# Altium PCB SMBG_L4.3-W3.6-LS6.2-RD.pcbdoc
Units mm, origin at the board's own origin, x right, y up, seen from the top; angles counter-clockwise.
Board outline 20.26 x 16.58 mm, 2 copper layers (Top Layer, Bottom Layer), stack 0 mm thick; 1 components, 0 nets, 2 pads, 0 vias.
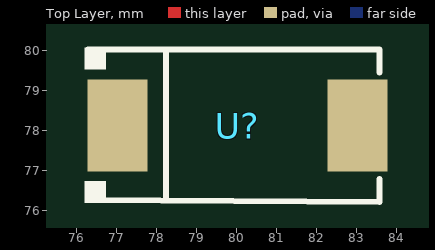
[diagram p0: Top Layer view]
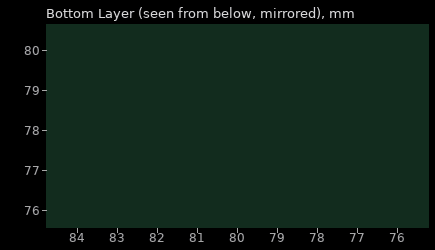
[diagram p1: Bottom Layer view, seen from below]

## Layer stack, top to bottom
Top Layer: signal copper (thickness not stored)
Bottom Layer: signal copper (thickness not stored)

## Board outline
90.112,69.85 69.85,69.85 69.85,86.43 90.112,86.43

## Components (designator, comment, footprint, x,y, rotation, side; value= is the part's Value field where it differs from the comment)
U? "" SMBG_L4.3-W3.6-LS6.2-RD 80.012,78.131 r0 top

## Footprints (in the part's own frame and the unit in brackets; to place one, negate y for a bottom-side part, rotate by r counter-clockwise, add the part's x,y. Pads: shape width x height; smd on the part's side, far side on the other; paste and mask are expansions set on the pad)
SMBG_L4.3-W3.6-LS6.2-RD [mm]
  rect 1.5x2.3 smd paste+0 mask+0.05: 1(-3,0) 2(3,0)
  silkscreen extent -3.81,-1.93 3.56,1.95

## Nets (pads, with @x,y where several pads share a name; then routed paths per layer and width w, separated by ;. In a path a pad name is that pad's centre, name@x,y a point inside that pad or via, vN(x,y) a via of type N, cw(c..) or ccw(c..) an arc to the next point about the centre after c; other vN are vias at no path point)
pads on no net: U?.1 U?.2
